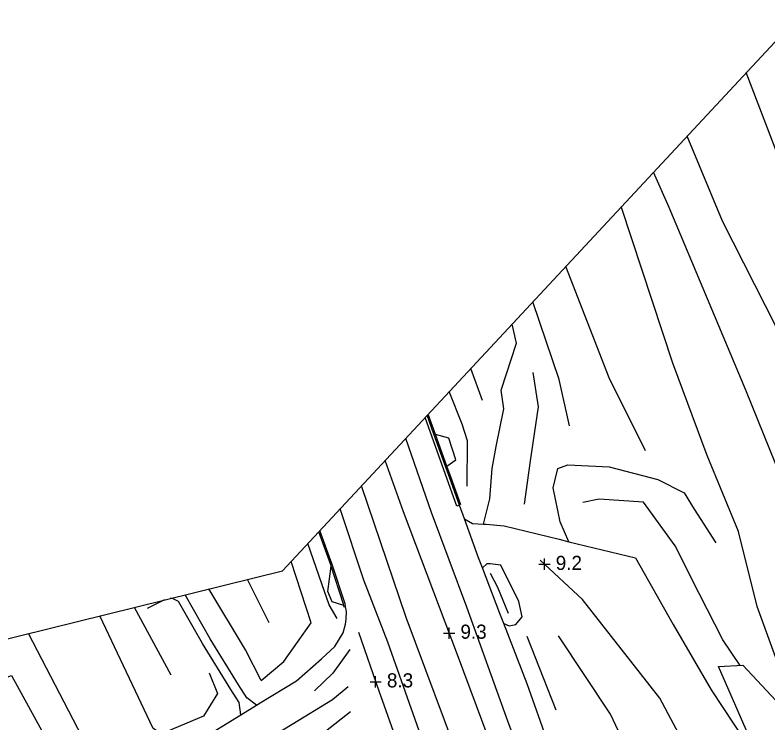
# Model space of a CAD drawing. Extents: x 2316231 to 2323598, y 363169 to 371906.
# Drawn here: x 2320840 to 2321107, y 366226.8 to 366477.6 of the extents above; entities that cross this region are included whole.
import ezdxf

# ---------------------------------------------------------------- set-up
doc = ezdxf.new("R2010")
doc.units = 0
for name, color, linetype in [('RD_DTM_BkLn1', 7, 'Continuous'), ('RD_DTM_Holes', 7, 'Continuous'), ('RD_DTM_TinHull', 7, 'Continuous'), ('RD_DTM_Void', 7, 'Continuous'), ('RD_EX_Road', 7, 'Continuous')]:
    doc.layers.add(name, color=color, linetype=linetype)

msp = doc.modelspace()

# ---------------------------------------------------------------- linework, layer by layer
at = {"layer": 'RD_DTM_BkLn1'}
for p, q in [((2321005.821, 366341.032), (2321001.629, 366352.438)), ((2320930.125, 366262.344), (2320922.423, 366277.681)), ((2320895.336, 366243.775), (2320882.358, 366267.789)), ((2321021.479, 366257.624), (2321031.742, 366231.536)), ((2321086.823, 366238.614), (2321106.687, 366208.725))]:
    msp.add_line(p, q, dxfattribs=at)
for points in [[(2321217.85, 366171.777), (2321195.092, 366221.773), (2321177.651, 366264.476), (2321159.843, 366311.615), (2321145.632, 366336.983), (2321130.053, 366374.015), (2321112.686, 366422.481), (2321099.314, 366457.31)], [(2321205.698, 366171.431), (2321181.155, 366219.069), (2321161.671, 366246.316), (2321145.676, 366287.224), (2321131.683, 366315.53), (2321109.87, 366367.188), (2321090.922, 366404.593), (2321078.335, 366434.787)], [(2321134.19, 366254.005), (2321123.83, 366281.237), (2321113.911, 366308.29), (2321099.216, 366344.744), (2321071.974, 366409.506), (2321066.365, 366421.937)], [(2321125.464, 366216.064), (2321116.283, 366232.078), (2321103.125, 366268.101), (2321096.609, 366294.63), (2321085.395, 366321.552), (2321073.241, 366354.302), (2321055.057, 366409.47), (2321054.967, 366409.7)], [(2321063.637, 366323.252), (2321050.689, 366349.125), (2321035.288, 366388.574)], [(2321036.583, 366332.059), (2321033.021, 366348.534), (2321023.662, 366376.092)], [(2321020.69, 366304.354), (2321022.86, 366319.693), (2321025.617, 366338.889), (2321023.705, 366351.001)], [(2321000.375, 366310.677), (2321000.474, 366326.835), (2320998.601, 366332.693), (2320994.011, 366344.26)], [(2321033.694, 366176.556), (2321014.739, 366227.476), (2321000.245, 366267.849), (2320987.723, 366301.395), (2320978.552, 366327.664)], [(2321028.335, 366166.59), (2320996.898, 366250.908), (2320977.715, 366301.627), (2320971.219, 366319.791)], [(2321016.422, 366163.653), (2320998.893, 366210.119), (2320978.695, 366264.205), (2320962.86, 366310.818)], [(2321097.192, 366247.24), (2321091.039, 366256.331), (2321082.634, 366272.652), (2321074.081, 366289.569), (2321062.906, 366305.08), (2321047.186, 366306.086), (2321041.345, 366304.995)], [(2321077.337, 366308.4), (2321080.843, 366302.531), (2321088.568, 366290.706)], [(2321004.904, 366165.864), (2320989.541, 366205.668), (2320983.367, 366224.027), (2320972.218, 366255.429), (2320963.723, 366277.362), (2320955.296, 366302.697)], [(2320927.348, 366241.829), (2320935.375, 366248.658), (2320945.012, 366262.335), (2320937.963, 366284.088)], [(2321090.1, 366195.438), (2321068.707, 366235.6), (2321041.272, 366270.543), (2321026.178, 366284.507)], [(2321008.471, 366279.844), (2321011.074, 366274.903), (2321014.872, 366265.719)], [(2320927.348, 366241.829), (2320921.694, 366252.753), (2320908.708, 366274.295)], [(2320908.91, 366244.592), (2320911.8, 366237.316), (2320906.845, 366229.218), (2320891.904, 366222.973), (2320888.988, 366224.825), (2320870.072, 366264.756)], [(2320877.59, 366214.66), (2320874.677, 366211.856), (2320867.033, 366209.703), (2320863.802, 366221.871), (2320844.759, 366258.506)], [(2320961.871, 366259), (2320969.008, 366238.161), (2320974.067, 366223.869)], [(2321072.431, 366184.855), (2321051.191, 366229.91), (2321032.738, 366257.71)], [(2320958.702, 366252.896), (2320952.671, 366244.456), (2320946.223, 366238.188)], [(2320842.457, 366166.734), (2320874.677, 366187.974), (2320916.629, 366213.296), (2320938.28, 366226.448), (2320952.538, 366235.147), (2320958.181, 366239.752)], [(2320959.006, 366230.751), (2320950.15, 366223.823), (2320940.181, 366216.226)]]:
    msp.add_lwpolyline(points, dxfattribs=at)
at = {"layer": 'RD_DTM_Holes'}
msp.add_lwpolyline([(2321158.426, 366176.083), (2321166.41, 366170.04), (2321183.862, 366166.03), (2321195.081, 366160.62), (2321197.85, 366148.543), (2321190.533, 366135.008), (2321176.38, 366129.7), (2321162.629, 366130.048), (2321147.956, 366146.598), (2321125.36, 366173.244), (2321103.426, 366214.922), (2321089.457, 366246.833), (2321098.094, 366247.287), (2321119.996, 366223.886), (2321147.771, 366184.157), (2321158.426, 366176.083)], dxfattribs=at)
at = {"layer": 'RD_DTM_TinHull'}
msp.add_lwpolyline([(2318009.783, 367630.234), (2318999.407, 367049.655), (2319281.252, 367000.442), (2319521.217, 366961.394), (2320716.689, 366226.888), (2320934.852, 366280.749), (2321141.465, 366502.562), (2321263.978, 366719.924), (2321282.537, 366948.249), (2321279.947, 367175.232), (2321214.652, 367465.641), (2321221.515, 367818.629), (2321207.427, 368150.673), (2321267.86, 368369.229), (2321400.963, 368599.408), (2321534.916, 368777.939)], dxfattribs=at)
at = {"layer": 'RD_DTM_Void'}
for p, q in [((2321027.763, 366281.04), (2321027.763, 366285.04)), ((2321025.763, 366283.04), (2321029.763, 366283.04)), ((2320993.964, 366256.664), (2320993.964, 366260.664)), ((2320991.964, 366258.664), (2320995.964, 366258.664)), ((2320967.892, 366239.422), (2320967.892, 366243.422)), ((2320965.892, 366241.422), (2320969.892, 366241.422))]:
    msp.add_line(p, q, dxfattribs=at)
at = {"layer": 'RD_EX_Road'}
for p, q in [((2320988.56, 366329.168), (2320986.163, 366335.835)), ((2320989.147, 366329.012), (2320986.547, 366336.247)), ((2320993.168, 366317.825), (2320989.147, 366329.012)), ((2320997.643, 366303.986), (2320996.703, 366303.645)), ((2320999.403, 366299.137), (2320997.643, 366303.986)), ((2320893.042, 366270.427), (2320886.849, 366267.336)), ((2320956.739, 366267.856), (2320956.633, 366268.48)), ((2320920.071, 366229.759), (2320925.599, 366233.146)), ((2320891.675, 366212.365), (2320920.071, 366229.759))]:
    msp.add_line(p, q, dxfattribs=at)
for points in [[(2321006.093, 366297.315), (2321008.372, 366306.294), (2321009.238, 366316.975), (2321010.633, 366324.723), (2321013.315, 366338.18), (2321012.415, 366344.72), (2321017.884, 366361.354), (2321016.273, 366368.159)], [(2320996.703, 366303.645), (2320993.236, 366313.203), (2320985.397, 366335.012)], [(2320997.643, 366303.986), (2320994.176, 366313.543), (2320988.56, 366329.168)], [(2320993.168, 366317.825), (2320996.344, 366320.026), (2320993.889, 366327.755), (2320989.147, 366329.012)], [(2320998.114, 366304.157), (2320994.647, 366313.712), (2320993.168, 366317.825)], [(2321036.444, 366291.05), (2321033.283, 366298.12), (2321030.834, 366310.188), (2321032.513, 366316.967), (2321036.023, 366318.32), (2321050.717, 366317.519), (2321067.919, 366313.108), (2321077.337, 366308.4)], [(2321005.765, 366281.779), (2321004.39, 366285.391), (2320999.403, 366299.137)], [(2320999.403, 366299.137), (2321002.245, 366297.527), (2321006.093, 366297.315)], [(2321006.093, 366297.315), (2321007.085, 366297.261), (2321013.486, 366296.68), (2321032.972, 366291.892), (2321036.444, 366291.05)], [(2320952.141, 366282.341), (2320951.972, 366282.854), (2320947.754, 366294.601)], [(2320957.232, 366267.94), (2320957.04, 366269.066), (2320952.445, 366283.016), (2320948.138, 366295.012)], [(2320954.204, 366263.812), (2320951.413, 366268.638), (2320948.828, 366276.111), (2320943.879, 366290.44)], [(2321036.444, 366291.05), (2321059.994, 366285.337), (2321073.342, 366261.667), (2321086.823, 366238.614)], [(2320956.633, 366268.48), (2320952.459, 366269.739), (2320950.944, 366273.355), (2320952.141, 366282.341)], [(2320956.633, 366268.48), (2320956.553, 366268.945), (2320952.141, 366282.341)], [(2321013.304, 366262.058), (2321015.239, 366261.271), (2321017.61, 366261.768), (2321019.822, 366264.483), (2321018.716, 366269.869), (2321012.317, 366282.746), (2321008.541, 366283.239), (2321007.28, 366283.178), (2321005.765, 366281.779)], [(2321013.304, 366262.058), (2321011.909, 366265.634), (2321005.765, 366281.779)], [(2320925.599, 366233.146), (2320922.205, 366235.77), (2320919.225, 366240.366), (2320909.222, 366256.624), (2320900.302, 366272.219)], [(2320920.071, 366229.759), (2320919.47, 366234.048), (2320916.493, 366238.64), (2320906.442, 366254.975), (2320897.952, 366269.818), (2320895.891, 366270.87), (2320895.003, 366270.911)], [(2320925.599, 366233.146), (2320926.886, 366233.934), (2320939.819, 366241.756), (2320948.658, 366249.547), (2320953.413, 366253.971), (2320956.432, 366258.734), (2320957.189, 366261.867), (2320957.469, 366263.615), (2320957.511, 366266.31), (2320957.232, 366267.94)], [(2321029.103, 366219.694), (2321021.643, 366240.682), (2321013.304, 366262.058)], [(2320851.985, 366186.238), (2320849.942, 366191.2), (2320840.345, 366208.953), (2320825.944, 366237.203), (2320833.219, 366241.564), (2320838.821, 366243.614), (2320850.781, 366221.726), (2320861.571, 366202.694), (2320867.629, 366196.662)]]:
    msp.add_lwpolyline(points, dxfattribs=at)

# ---------------------------------------------------------------- texts
at = {"layer": 'RD_DTM_Void'}
for s, p in [('9.2', (2321031.763, 366281.04)), ('9.3', (2320997.964, 366256.664)), ('8.3', (2320971.892, 366239.422))]:
    msp.add_text(s, height=5, dxfattribs=at).set_placement(p)

doc.saveas('drawing.dxf')
